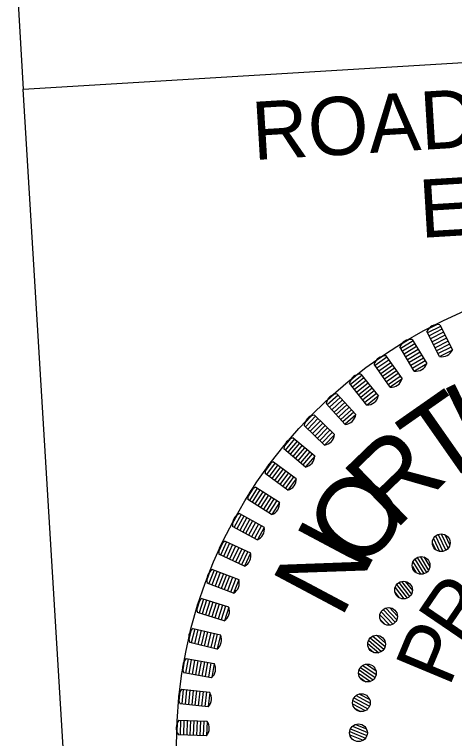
# Model space of a CAD drawing. Extents: x 2111349 to 2114115, y 669753 to 671326.
# Drawn here: x 2113635.5 to 2113673.4, y 670818.6 to 670880.9 of the extents above; entities that cross this region are included whole.
import ezdxf

# ---------------------------------------------------------------- set-up
doc = ezdxf.new("R2010")
doc.units = 0
doc.layers.add('Exist Roads Curbs Text', color=7, linetype='Continuous')
doc.layers.add('Exist Vegetation Woods Line Text', color=7, linetype='Continuous')

msp = doc.modelspace()

# ---------------------------------------------------------------- linework, layer by layer
at = {"layer": 'Exist Roads Curbs Text'}
msp.add_line((2113635.539, 670886.955), (2113636.295, 670874.478), dxfattribs=at)
msp.add_lwpolyline([(2113636.295, 670874.478), (2113736.162, 670880.53), (2113742.968, 670768.236), (2113643.101, 670762.184)], close=True, dxfattribs=at)
at = {"layer": 'Exist Vegetation Woods Line Text'}
for p, q in [((2113671.825, 670854.213), (2113671.147, 670853.865)), ((2113672.105, 670854.202), (2113673.209, 670852.051)), ((2113672.096, 670851.481), (2113670.993, 670853.631)), ((2113672.172, 670854.071), (2113671.06, 670853.5)), ((2113672.303, 670853.817), (2113671.19, 670853.246)), ((2113672.433, 670853.563), (2113671.321, 670852.992)), ((2113669.473, 670852.934), (2113668.82, 670852.543)), ((2113669.753, 670852.942), (2113670.996, 670850.869)), ((2113672.563, 670853.309), (2113671.451, 670852.738)), ((2113672.693, 670853.055), (2113671.581, 670852.485)), ((2113669.924, 670850.226), (2113668.681, 670852.299)), ((2113669.829, 670852.816), (2113668.757, 670852.172)), ((2113669.976, 670852.571), (2113668.904, 670851.928)), ((2113670.122, 670852.326), (2113669.05, 670851.683)), ((2113672.824, 670852.802), (2113671.711, 670852.231)), ((2113672.954, 670852.548), (2113671.842, 670851.977)), ((2113673.084, 670852.294), (2113671.972, 670851.723)), ((2113670.269, 670852.082), (2113669.197, 670851.439)), ((2113670.416, 670851.837), (2113669.344, 670851.194)), ((2113673.201, 670852.033), (2113672.116, 670851.477)), ((2113667.573, 670851.408), (2113666.546, 670850.696)), ((2113667.21, 670851.503), (2113666.584, 670851.069)), ((2113667.736, 670851.174), (2113666.709, 670850.461)), ((2113667.489, 670851.529), (2113668.867, 670849.543)), ((2113670.563, 670851.592), (2113669.49, 670850.949)), ((2113670.709, 670851.348), (2113669.637, 670850.705)), ((2113670.856, 670851.103), (2113669.784, 670850.46)), ((2113667.84, 670848.831), (2113666.462, 670850.817)), ((2113667.899, 670850.94), (2113666.871, 670850.227)), ((2113668.061, 670850.705), (2113667.034, 670849.993)), ((2113668.224, 670850.471), (2113667.197, 670849.758)), ((2113670.989, 670850.851), (2113669.944, 670850.223)), ((2113665.416, 670849.855), (2113664.438, 670849.076)), ((2113665.047, 670849.926), (2113664.451, 670849.452)), ((2113665.324, 670849.97), (2113666.83, 670848.08)), ((2113668.386, 670850.236), (2113667.359, 670849.524)), ((2113668.549, 670850.002), (2113667.522, 670849.29)), ((2113668.711, 670849.768), (2113667.684, 670849.055)), ((2113665.852, 670847.301), (2113664.346, 670849.192)), ((2113665.594, 670849.632), (2113664.616, 670848.853)), ((2113665.771, 670849.409), (2113664.793, 670848.63)), ((2113665.949, 670849.186), (2113664.971, 670848.407)), ((2113668.861, 670849.524), (2113667.86, 670848.83)), ((2113666.127, 670848.963), (2113665.149, 670848.184)), ((2113666.304, 670848.74), (2113665.327, 670847.961)), ((2113662.993, 670848.209), (2113662.43, 670847.696)), ((2113663.366, 670848.163), (2113662.442, 670847.321)), ((2113663.558, 670847.952), (2113662.634, 670847.11)), ((2113663.267, 670848.272), (2113664.894, 670846.485)), ((2113666.482, 670848.516), (2113665.504, 670847.738)), ((2113666.66, 670848.293), (2113665.682, 670847.514)), ((2113666.825, 670848.06), (2113665.872, 670847.301)), ((2113663.97, 670845.643), (2113662.342, 670847.43)), ((2113663.75, 670847.741), (2113662.826, 670846.899)), ((2113663.942, 670847.53), (2113663.018, 670846.688)), ((2113664.134, 670847.319), (2113663.21, 670846.477)), ((2113664.326, 670847.108), (2113663.402, 670846.267)), ((2113664.518, 670846.897), (2113663.594, 670846.056)), ((2113664.71, 670846.687), (2113663.786, 670845.845)), ((2113661.057, 670846.36), (2113660.529, 670845.812)), ((2113661.432, 670846.339), (2113660.565, 670845.438)), ((2113661.638, 670846.141), (2113660.771, 670845.24)), ((2113661.326, 670846.441), (2113663.068, 670844.765)), ((2113664.891, 670846.465), (2113663.99, 670845.644)), ((2113662.201, 670843.864), (2113660.459, 670845.54)), ((2113661.843, 670845.943), (2113660.977, 670845.042)), ((2113662.049, 670845.745), (2113661.182, 670844.844)), ((2113662.254, 670845.548), (2113661.388, 670844.647)), ((2113662.46, 670845.35), (2113661.593, 670844.449)), ((2113662.665, 670845.152), (2113661.799, 670844.251)), ((2113662.871, 670844.954), (2113662.004, 670844.053)), ((2113659.247, 670844.388), (2113658.757, 670843.805)), ((2113659.623, 670844.391), (2113658.818, 670843.434)), ((2113659.841, 670844.207), (2113659.036, 670843.251)), ((2113659.51, 670844.486), (2113661.359, 670842.929)), ((2113663.066, 670844.746), (2113662.221, 670843.867)), ((2113660.059, 670844.023), (2113659.254, 670843.067)), ((2113660.278, 670843.84), (2113659.472, 670842.883)), ((2113660.496, 670843.656), (2113659.691, 670842.7)), ((2113660.554, 670841.973), (2113658.705, 670843.529)), ((2113660.714, 670843.472), (2113659.909, 670842.516)), ((2113660.932, 670843.288), (2113660.127, 670842.332)), ((2113661.15, 670843.105), (2113660.345, 670842.148)), ((2113657.572, 670842.299), (2113657.121, 670841.686)), ((2113657.947, 670842.327), (2113657.206, 670841.32)), ((2113657.828, 670842.415), (2113659.776, 670840.984)), ((2113661.359, 670842.909), (2113660.573, 670841.976)), ((2113658.176, 670842.159), (2113657.436, 670841.151)), ((2113658.406, 670841.99), (2113657.666, 670840.982)), ((2113658.636, 670841.821), (2113657.896, 670840.813)), ((2113659.035, 670839.976), (2113657.088, 670841.407)), ((2113658.866, 670841.652), (2113658.126, 670840.644)), ((2113659.096, 670841.483), (2113658.356, 670840.476)), ((2113659.326, 670841.314), (2113658.586, 670840.307)), ((2113659.556, 670841.145), (2113658.816, 670840.138)), ((2113659.776, 670840.964), (2113659.055, 670839.981)), ((2113656.038, 670840.105), (2113655.629, 670839.463)), ((2113656.41, 670840.158), (2113655.738, 670839.104)), ((2113656.651, 670840.005), (2113655.979, 670838.95)), ((2113656.891, 670839.851), (2113656.219, 670838.797)), ((2113656.286, 670840.237), (2113658.324, 670838.938)), ((2113657.652, 670837.884), (2113655.614, 670839.183)), ((2113657.132, 670839.698), (2113656.46, 670838.644)), ((2113657.372, 670839.545), (2113656.7, 670838.49)), ((2113657.613, 670839.391), (2113656.941, 670838.337)), ((2113657.854, 670839.238), (2113657.182, 670838.184)), ((2113658.094, 670839.085), (2113657.422, 670838.03)), ((2113658.326, 670838.918), (2113657.671, 670837.89)), ((2113654.892, 670837.962), (2113657.011, 670836.801)), ((2113654.653, 670837.814), (2113654.287, 670837.147)), ((2113655.021, 670837.892), (2113654.42, 670836.795)), ((2113655.271, 670837.754), (2113654.67, 670836.658)), ((2113655.521, 670837.617), (2113654.92, 670836.521)), ((2113655.771, 670837.48), (2113655.17, 670836.384)), ((2113656.021, 670837.343), (2113655.42, 670836.247)), ((2113656.41, 670835.704), (2113654.291, 670836.866)), ((2113656.271, 670837.206), (2113655.671, 670836.11)), ((2113656.522, 670837.069), (2113655.921, 670835.973)), ((2113656.772, 670836.932), (2113656.171, 670835.836)), ((2113657.014, 670836.781), (2113656.429, 670835.712)), ((2113671.968, 670836.174), (2113672.621, 670834.803)), ((2113672.226, 670836.222), (2113672.821, 670834.972)), ((2113672.537, 670836.16), (2113672.969, 670835.253)), ((2113653.784, 670835.538), (2113653.257, 670834.405)), ((2113653.65, 670835.6), (2113655.842, 670834.581)), ((2113671.569, 670835.829), (2113672.102, 670834.71)), ((2113671.747, 670836.045), (2113672.383, 670834.712)), ((2113653.422, 670835.437), (2113653.101, 670834.747)), ((2113654.043, 670835.418), (2113653.516, 670834.285)), ((2113654.301, 670835.298), (2113653.774, 670834.164)), ((2113654.56, 670835.177), (2113654.033, 670834.044)), ((2113654.819, 670835.057), (2113654.292, 670833.924)), ((2113655.077, 670834.937), (2113654.55, 670833.803)), ((2113671.474, 670835.438), (2113671.739, 670834.882)), ((2113655.315, 670833.448), (2113653.123, 670834.467)), ((2113655.336, 670834.817), (2113654.809, 670833.683)), ((2113655.595, 670834.696), (2113655.068, 670833.563)), ((2113655.847, 670834.562), (2113655.333, 670833.457)), ((2113670.421, 670834.268), (2113671.144, 670833.087)), ((2113670.736, 670834.239), (2113671.261, 670833.382)), ((2113669.808, 670833.808), (2113670.456, 670832.751)), ((2113669.963, 670834.042), (2113670.734, 670832.783)), ((2113670.169, 670834.192), (2113670.962, 670832.897)), ((2113652.351, 670832.984), (2113652.077, 670832.273)), ((2113652.706, 670833.109), (2113652.255, 670831.943)), ((2113652.972, 670833.006), (2113652.521, 670831.84)), ((2113652.568, 670833.162), (2113654.822, 670832.29)), ((2113669.755, 670833.409), (2113670.076, 670832.884)), ((2113653.238, 670832.903), (2113652.787, 670831.737)), ((2113653.504, 670832.8), (2113653.053, 670831.634)), ((2113653.77, 670832.697), (2113653.319, 670831.531)), ((2113654.036, 670832.594), (2113653.585, 670831.428)), ((2113654.302, 670832.491), (2113653.851, 670831.325)), ((2113654.568, 670832.388), (2113654.117, 670831.222)), ((2113654.371, 670831.124), (2113652.117, 670831.996)), ((2113654.828, 670832.271), (2113654.388, 670831.134)), ((2113668.398, 670831.863), (2113669.297, 670830.691)), ((2113668.587, 670832.034), (2113669.511, 670830.829)), ((2113668.83, 670832.135), (2113669.672, 670831.037)), ((2113669.147, 670832.14), (2113669.758, 670831.342)), ((2113668.257, 670831.212), (2113668.632, 670830.724)), ((2113668.269, 670831.614), (2113669.023, 670830.63)), ((2113651.445, 670830.465), (2113651.218, 670829.738)), ((2113651.79, 670830.613), (2113651.417, 670829.42)), ((2113651.649, 670830.657), (2113653.956, 670829.936)), ((2113652.062, 670830.528), (2113651.689, 670829.334)), ((2113652.334, 670830.443), (2113651.962, 670829.249)), ((2113652.607, 670830.357), (2113652.234, 670829.164)), ((2113652.879, 670830.272), (2113652.506, 670829.079)), ((2113653.151, 670830.187), (2113652.778, 670828.994)), ((2113653.424, 670830.102), (2113653.051, 670828.909)), ((2113653.696, 670830.017), (2113653.323, 670828.824)), ((2113653.963, 670829.917), (2113653.6, 670828.754)), ((2113667.47, 670829.848), (2113668.423, 670828.844)), ((2113667.785, 670829.886), (2113668.477, 670829.156)), ((2113653.583, 670828.742), (2113651.276, 670829.464)), ((2113666.967, 670829.272), (2113667.82, 670828.372)), ((2113667.07, 670829.532), (2113668.086, 670828.461)), ((2113667.24, 670829.722), (2113668.285, 670828.62)), ((2113666.998, 670828.87), (2113667.421, 670828.424)), ((2113651.041, 670828.062), (2113650.748, 670826.847)), ((2113650.898, 670828.096), (2113653.248, 670827.529)), ((2113651.319, 670827.995), (2113651.025, 670826.78)), ((2113650.707, 670827.891), (2113650.528, 670827.151)), ((2113651.596, 670827.928), (2113651.303, 670826.713)), ((2113651.873, 670827.861), (2113651.58, 670826.646)), ((2113652.151, 670827.794), (2113651.857, 670826.579)), ((2113652.428, 670827.727), (2113652.135, 670826.512)), ((2113652.705, 670827.66), (2113652.412, 670826.445)), ((2113652.982, 670827.593), (2113652.689, 670826.378)), ((2113653.256, 670827.511), (2113652.97, 670826.326)), ((2113666.357, 670827.432), (2113667.41, 670826.532)), ((2113666.667, 670827.502), (2113667.431, 670826.849)), ((2113652.954, 670826.314), (2113650.605, 670826.881)), ((2113665.917, 670826.806), (2113666.86, 670826)), ((2113665.992, 670827.076), (2113667.115, 670826.116)), ((2113666.141, 670827.282), (2113667.296, 670826.296)), ((2113665.99, 670826.409), (2113666.457, 670826.01)), ((2113650.318, 670825.492), (2113652.7, 670825.082)), ((2113650.14, 670825.275), (2113650.011, 670824.524)), ((2113650.463, 670825.467), (2113650.251, 670824.235)), ((2113650.744, 670825.419), (2113650.532, 670824.187)), ((2113651.025, 670825.37), (2113650.813, 670824.138)), ((2113651.306, 670825.322), (2113651.094, 670824.09)), ((2113651.587, 670825.273), (2113651.375, 670824.041)), ((2113651.869, 670825.225), (2113651.656, 670823.993)), ((2113652.15, 670825.176), (2113651.937, 670823.945)), ((2113652.431, 670825.128), (2113652.218, 670823.896)), ((2113652.709, 670825.064), (2113652.502, 670823.863)), ((2113665.503, 670824.912), (2113666.644, 670824.128)), ((2113665.803, 670825.014), (2113666.632, 670824.444)), ((2113652.487, 670823.85), (2113650.105, 670824.26)), ((2113665.131, 670824.243), (2113666.153, 670823.541)), ((2113665.177, 670824.52), (2113666.394, 670823.683)), ((2113665.304, 670824.741), (2113666.555, 670823.88)), ((2113665.244, 670823.857), (2113665.751, 670823.508)), ((2113649.748, 670822.627), (2113649.669, 670821.869)), ((2113649.911, 670822.855), (2113652.314, 670822.603)), ((2113650.057, 670822.84), (2113649.927, 670821.597)), ((2113650.341, 670822.81), (2113650.211, 670821.567)), ((2113650.625, 670822.78), (2113650.494, 670821.537)), ((2113650.908, 670822.751), (2113650.778, 670821.507)), ((2113651.192, 670822.721), (2113651.062, 670821.478)), ((2113651.476, 670822.691), (2113651.345, 670821.448)), ((2113651.76, 670822.661), (2113651.629, 670821.418)), ((2113652.043, 670822.631), (2113651.913, 670821.388)), ((2113652.325, 670822.586), (2113652.198, 670821.374)), ((2113665.205, 670822.45), (2113666.088, 670821.97)), ((2113664.634, 670821.893), (2113665.932, 670821.188)), ((2113664.737, 670822.126), (2113666.071, 670821.401)), ((2113664.917, 670822.317), (2113666.134, 670821.656)), ((2113652.184, 670821.36), (2113649.78, 670821.612)), ((2113664.617, 670821.613), (2113665.706, 670821.021)), ((2113664.77, 670821.24), (2113665.31, 670820.947)), ((2113649.532, 670819.958), (2113649.503, 670819.197)), ((2113649.679, 670820.197), (2113652.094, 670820.104)), ((2113649.826, 670820.192), (2113649.778, 670818.942)), ((2113650.111, 670820.181), (2113650.063, 670818.931)), ((2113650.396, 670820.17), (2113650.348, 670818.92)), ((2113650.681, 670820.159), (2113650.633, 670818.91)), ((2113650.966, 670820.148), (2113650.918, 670818.899)), ((2113651.251, 670820.137), (2113651.203, 670818.888)), ((2113651.537, 670820.126), (2113651.488, 670818.877)), ((2113651.822, 670820.115), (2113651.774, 670818.866)), ((2113652.106, 670820.088), (2113652.059, 670818.87)), ((2113664.446, 670819.466), (2113665.849, 670818.884)), ((2113664.605, 670819.675), (2113665.884, 670819.145)), ((2113664.878, 670819.837), (2113665.807, 670819.452)), ((2113652.046, 670818.855), (2113649.631, 670818.948)), ((2113664.368, 670819.223), (2113665.732, 670818.658)), ((2113664.38, 670818.943), (2113665.526, 670818.468))]:
    msp.add_line(p, q, dxfattribs=at)
for centre, radius in [((2113690.024, 670818.026), 40.556), ((2113672.236, 670835.46), 0.762), ((2113670.51, 670833.511), 0.762), ((2113668.998, 670831.392), 0.762), ((2113667.715, 670829.127), 0.762), ((2113666.676, 670826.74), 0.762), ((2113665.893, 670824.257), 0.762), ((2113665.373, 670821.706), 0.762), ((2113665.123, 670819.115), 0.762)]:
    msp.add_circle(centre, radius, dxfattribs=at)
for centre, radius, start, end in [((2113671.924, 670853.185), 1.032, 79.89626, 154.43723), ((2113669.64, 670851.916), 1.032, 83.68573, 158.2267), ((2113672.306, 670852.441), 0.983, 257.67, 336.66349), ((2113667.444, 670850.498), 1.032, 87.4752, 162.01617), ((2113670.07, 670851.198), 0.983, 261.45947, 340.45296), ((2113665.347, 670848.938), 1.032, 91.26468, 165.80565), ((2113667.921, 670849.81), 0.983, 265.24894, 344.24243), ((2113663.358, 670847.244), 1.032, 95.05415, 169.59512), ((2113665.868, 670848.284), 0.983, 269.03842, 348.03191), ((2113661.485, 670845.421), 1.032, 98.84363, 173.38459), ((2113663.921, 670846.625), 0.983, 272.82789, 351.82138), ((2113659.736, 670843.478), 1.032, 102.6331, 177.17407), ((2113662.088, 670844.841), 0.983, 276.61736, 355.61086), ((2113660.376, 670842.939), 0.983, 280.40684, 359.40033), ((2113658.12, 670841.425), 1.032, 106.42257, 180.96354), ((2113658.794, 670840.929), 0.983, 284.19631, 3.1898), ((2113656.643, 670839.268), 1.032, 110.21205, 184.75302), ((2113657.349, 670838.818), 0.983, 287.98578, 6.97928), ((2113655.311, 670837.019), 1.032, 114.00152, 188.54249), ((2113656.046, 670836.617), 0.983, 291.77526, 10.76875), ((2113654.132, 670834.687), 1.032, 117.79099, 192.33196), ((2113654.891, 670834.334), 0.983, 295.56473, 14.55822), ((2113653.109, 670832.282), 1.032, 121.58047, 196.12144), ((2113653.889, 670831.98), 0.983, 299.35421, 18.3477), ((2113652.247, 670829.815), 1.032, 125.36994, 199.91091), ((2113653.046, 670829.565), 0.983, 303.14368, 22.13717), ((2113651.55, 670827.296), 1.032, 129.15942, 203.70038), ((2113652.364, 670827.1), 0.983, 306.93315, 25.92665), ((2113651.021, 670824.737), 1.032, 132.94889, 207.48986), ((2113651.846, 670824.595), 0.983, 310.72263, 29.71612), ((2113650.663, 670822.148), 1.032, 136.73836, 211.27933), ((2113651.495, 670822.061), 0.983, 314.5121, 33.50559), ((2113650.476, 670819.541), 1.032, 140.52784, 215.0688), ((2113651.312, 670819.509), 0.983, 318.30157, 37.29507)]:
    msp.add_arc(centre, radius, start, end, dxfattribs=at)

# ---------------------------------------------------------------- texts
at = {"layer": 'Exist Roads Curbs Text'}
for s, p in [('ROADWAY DESIGN', (2113656.101, 670868.365)), ('ENGINEER', (2113670.483, 670861.672))]:
    msp.add_text(s, height=5.0001, rotation=3.46824, dxfattribs=at).set_placement(p)
at = {"layer": 'Exist Vegetation Woods Line Text'}
for s, height, rotation, p in [('H', 6.846, 25.98253, (2113674.968, 670842.255)), ('T', 6.846, 34.98253, (2113672.003, 670840.059)), ('R', 6.846, 43.98253, (2113668.214, 670836.433)), ('O', 6.846, 52.98253, (2113665.602, 670832.804)), ('N', 6.846, 61.98253, (2113663.59, 670828.81)), ('R', 5.135, 55.7406, (2113674.254, 670826.286)), ('P', 5.135, 67.3535, (2113672.912, 670822.954))]:
    msp.add_text(s, height=height, rotation=rotation, dxfattribs=at).set_placement(p)

doc.saveas('drawing.dxf')
